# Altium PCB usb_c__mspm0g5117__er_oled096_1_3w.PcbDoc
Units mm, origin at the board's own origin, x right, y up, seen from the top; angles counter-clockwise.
Board outline 64 x 33 mm, 2 copper layers (Top, Bottom), stack 0 mm thick; 30 components, 30 nets, 189 pads, 73 vias.
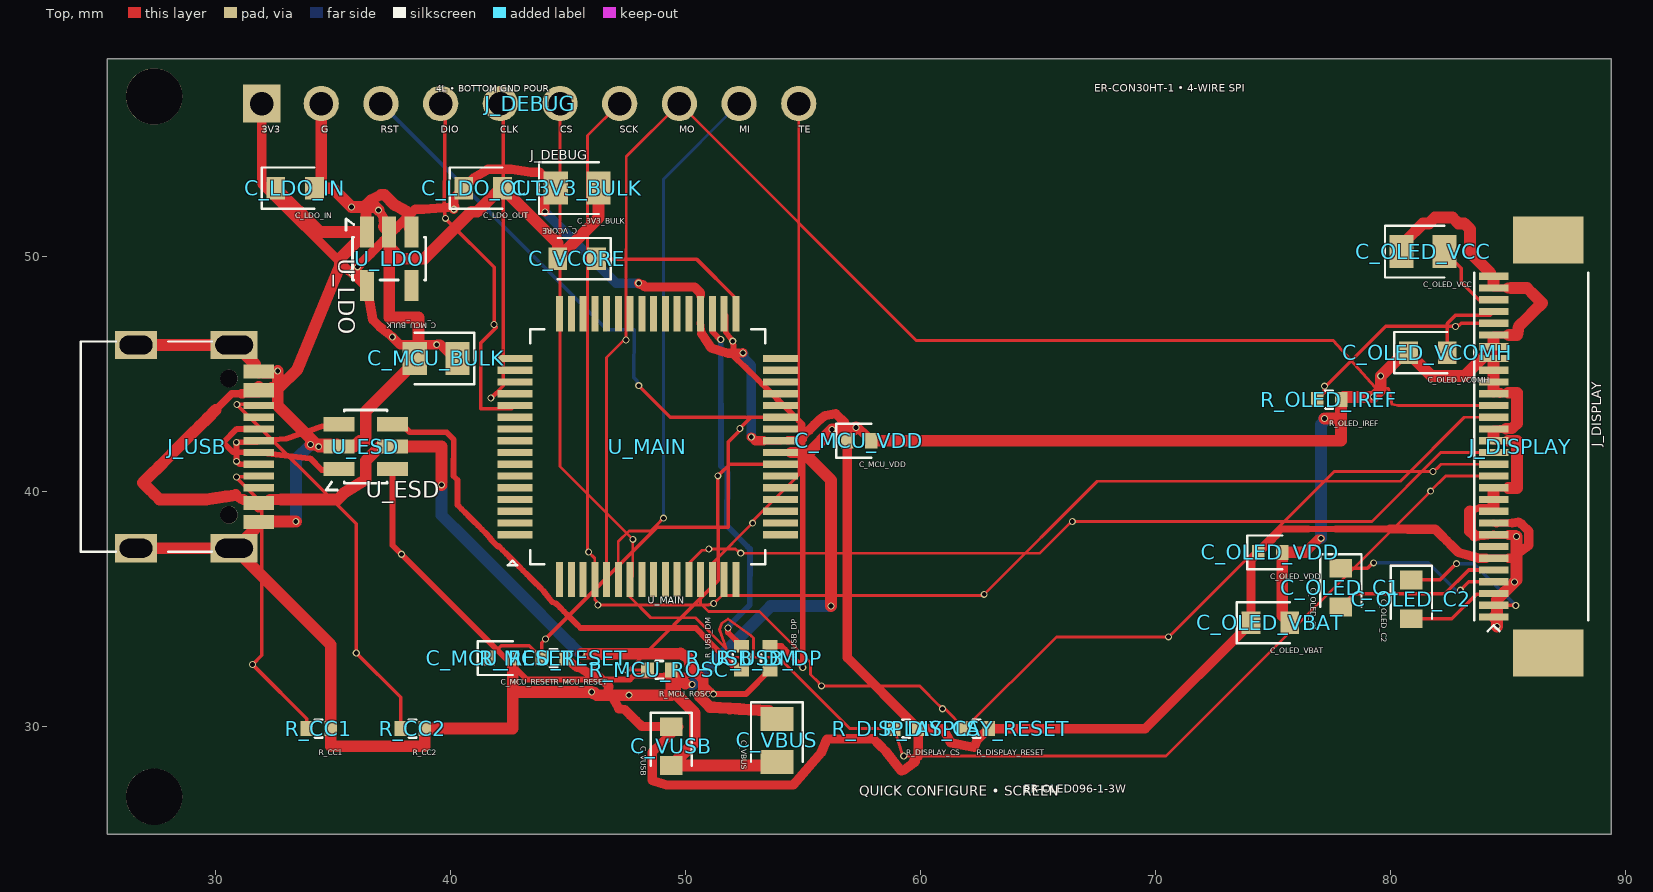
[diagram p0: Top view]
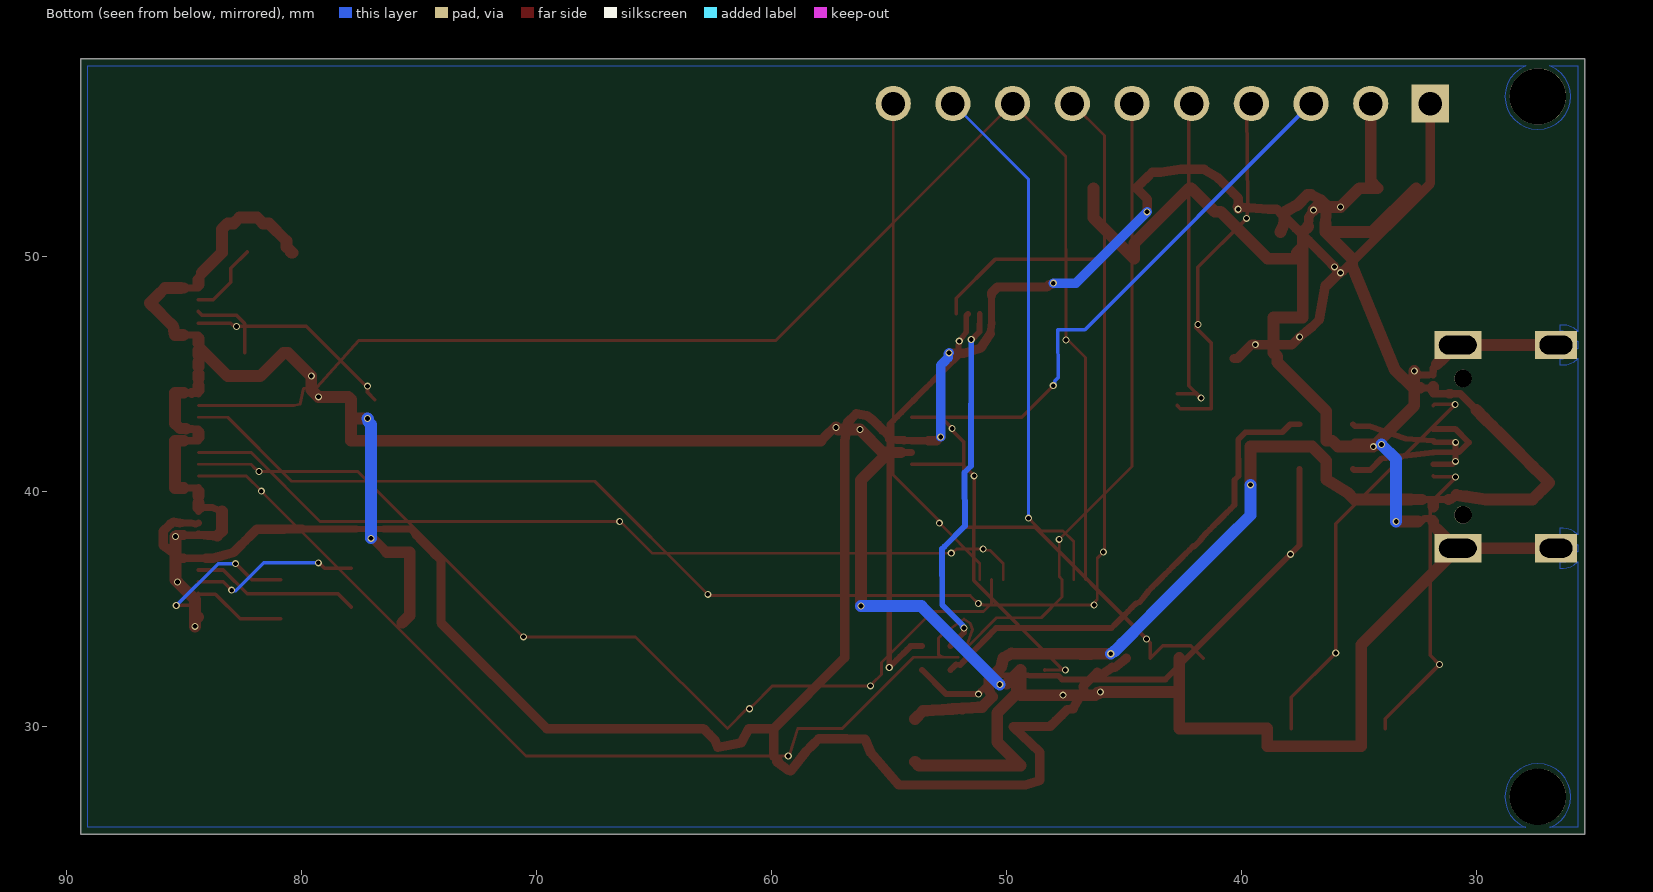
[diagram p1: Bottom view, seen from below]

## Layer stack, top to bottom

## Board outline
25.4,58.4 89.4,58.4 89.4,25.4 25.4,25.4

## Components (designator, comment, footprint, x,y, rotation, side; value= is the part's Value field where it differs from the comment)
C_3V3_BULK "" TSCIRCUIT-2.8500x1.4000mm 45.4,52.9 r0 top
C_LDO_IN "" TSCIRCUIT-2.4500x0.9500mm 33.4,52.9 r0 top
C_LDO_OUT "" TSCIRCUIT-2.4500x0.9500mm 41.4,52.9 r0 top
C_MCU_BULK "" TSCIRCUIT-2.8500x1.4000mm 39.4,45.65 r180 top
C_MCU_RESET "" TSCIRCUIT-1.5600x0.6400mm 42.15,32.9 r0 top
C_MCU_VDD "" TSCIRCUIT-1.5600x0.6400mm 57.4,42.15 r0 top
C_OLED_C1 "" TSCIRCUIT-0.9500x2.4500mm 77.9,35.9 r270 top
C_OLED_C2 "" TSCIRCUIT-0.9500x2.4500mm 80.9,35.4 r270 top
C_OLED_VBAT "" TSCIRCUIT-2.4500x0.9500mm 74.9,34.4 r0 top
C_OLED_VCC "" TSCIRCUIT-2.8500x1.4000mm 81.4,50.2 r0 top
C_OLED_VCOMH "" TSCIRCUIT-2.4500x0.9500mm 81.6,45.9 r0 top
C_OLED_VDD "" TSCIRCUIT-1.5600x0.6400mm 74.9,37.4 r0 top
C_VBUS "" TSCIRCUIT-1.4000x2.8500mm 53.9,29.4 r270 top
C_VCORE "" TSCIRCUIT-2.4500x0.9500mm 45.4,49.9 r180 top
C_VUSB "" TSCIRCUIT-0.9500x2.4500mm 49.4,29.15 r270 top
J_DEBUG "" TSCIRCUIT-24.3600x1.5000mm 43.4,56.5 r0 top
J_DISPLAY "" TSCIRCUIT-4.4500x19.5800mm 86,41.9 r90 top
J_USB "" TSCIRCUIT-6.7732x9.8502mm 29.112,41.9 r90 top
R_CC1 "" TSCIRCUIT-1.5600x0.6400mm 34.4,29.9 r0 top
R_CC2 "" TSCIRCUIT-1.5600x0.6400mm 38.4,29.9 r0 top
R_DISPLAY_CS "" TSCIRCUIT-1.5600x0.6400mm 59.4,29.9 r0 top
R_DISPLAY_RESET "" TSCIRCUIT-1.5600x0.6400mm 62.4,29.9 r0 top
R_MCU_RESET "" TSCIRCUIT-1.5600x0.6400mm 44.4,32.9 r0 top
R_MCU_ROSC "" TSCIRCUIT-1.5600x0.6400mm 48.9,32.4 r0 top
R_OLED_IREF "" TSCIRCUIT-1.5600x0.6400mm 77.4,43.9 r0 top
R_USB_DM "" TSCIRCUIT-0.6400x1.5600mm 52.4,32.9 r90 top
R_USB_DP "" TSCIRCUIT-0.6400x1.5600mm 53.6,32.9 r90 top
U_ESD "" TSCIRCUIT-3.6000x2.5000mm 36.4,41.9 r0 top
U_LDO "" TSCIRCUIT-2.5000x3.6000mm 37.4,49.9 r270 top
U_MAIN "" TSCIRCUIT-12.8000x12.8000mm 48.4,41.9 r0 top

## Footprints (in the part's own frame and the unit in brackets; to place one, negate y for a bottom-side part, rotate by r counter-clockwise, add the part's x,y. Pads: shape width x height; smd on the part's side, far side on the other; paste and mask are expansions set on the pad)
TSCIRCUIT-0.6400x1.5600mm [mm]
  rect 0.54x0.64 smd: 1(-0.51,0) 2(0.51,0)
  silkscreen extent -0.15,-0.38 0.15,0.38
TSCIRCUIT-0.9500x2.4500mm [mm]
  rect 0.8x0.95 smd: 1(-0.825,0) 2(0.825,0)
  silkscreen extent -1.43,-0.87 0.82,0.88
TSCIRCUIT-1.4000x2.8500mm [mm]
  rect 1.025x1.4 smd: 1(-0.913,0) 2(0.913,0)
  silkscreen extent -1.63,-1.1 0.91,1.1
TSCIRCUIT-1.5600x0.6400mm [mm]
  rect 0.54x0.64 smd: 1(-0.51,0) 2(0.51,0)
  silkscreen extent -0.98,-0.72 0.51,0.72
TSCIRCUIT-2.4500x0.9500mm [mm]
  rect 0.8x0.95 smd: 1(-0.825,0) 2(0.825,0)
  silkscreen extent -1.42,-0.88 0.82,0.87
TSCIRCUIT-2.5000x3.6000mm [mm]
  rect 1.325x0.6 smd: 1(-1.138,-0.95) 2(-1.138,0) 3(-1.138,0.95) 4(1.137,0.95) 5(1.137,-0.95)
  silkscreen extent -1.69,-1.84 0.91,1.56
TSCIRCUIT-2.8500x1.4000mm [mm]
  rect 1.025x1.4 smd: 1(-0.913,0) 2(0.913,0)
  silkscreen extent -1.63,-1.1 0.91,1.1
TSCIRCUIT-3.6000x2.5000mm [mm]
  rect 1.325x0.6 smd: 1(-1.138,-0.95) 2(-1.138,0) 3(-1.138,0.95) 4(1.137,0.95) 5(1.137,0) 6(1.137,-0.95)
  silkscreen extent -1.69,-1.84 0.91,1.56
TSCIRCUIT-4.4500x19.5800mm [mm]
  rect 0.3x1.25 smd: 1(-7.25,1.6) 2(-6.75,1.6) 3(-6.25,1.6) 4(-5.75,1.6) 5(-5.25,1.6) 6(-4.75,1.6) 7(-4.25,1.6) 8(-3.75,1.6) 9(-3.25,1.6) 10(-2.75,1.6) 11(-2.25,1.6) 12(-1.75,1.6) 13(-1.25,1.6) 14(-0.75,1.6) 15(-0.25,1.6) 16(0.25,1.6) 17(0.75,1.6) 18(1.25,1.6) 19(1.75,1.6) 20(2.25,1.6) 21(2.75,1.6) 22(3.25,1.6) 23(3.75,1.6) 24(4.25,1.6) 25(4.75,1.6) 26(5.25,1.6) 27(5.75,1.6) 28(6.25,1.6) 29(6.75,1.6) 30(7.25,1.6)
  rect 2x3 smd: 31(8.79,-0.725) 32(-8.79,-0.725)
  silkscreen extent -7.85,-2.42 7.4,2.43
TSCIRCUIT-6.7732x9.8502mm [mm]
  rect 0.3x1.3 smd: 1(-3.35,-2.737) 2(-3.05,-2.737) 3(-2.55,-2.737) 4(-2.25,-2.737) 5(-1.75,-2.737) 6(-1.25,-2.737) 7(-0.75,-2.737) 8(-0.25,-2.737) 9(0.25,-2.737) 10(0.75,-2.737) 11(1.25,-2.737) 12(1.75,-2.737) 13(2.55,-2.737) 14(2.25,-2.737) 15(3.35,-2.737) 16(3.05,-2.737)
  rect 1.2x2 hole 0.8 slot 1.6 at 90 deg: 17(-4.325,-1.693) 18(4.325,-1.693)
  rect 1.2x1.8 hole 0.8 slot 1.4 at 90 deg: 19(4.325,2.487) 20(-4.325,2.487)
  round 0.75 hole 0.75 unplated: NPTH-1(-2.9,-1.468) NPTH-2(2.9,-1.468)
  silkscreen extent -4.47,-0.75 4.47,4.83
TSCIRCUIT-12.8000x12.8000mm [mm]
  rect 1.5x0.3 smd: 1(-5.65,-3.75) 2(-5.65,-3.25) 3(-5.65,-2.75) 4(-5.65,-2.25) 5(-5.65,-1.75) 6(-5.65,-1.25) 7(-5.65,-0.75) 8(-5.65,-0.25) 9(-5.65,0.25) 10(-5.65,0.75) 11(-5.65,1.25) 12(-5.65,1.75) 13(-5.65,2.25) 14(-5.65,2.75) 15(-5.65,3.25) 16(-5.65,3.75) 33(5.65,3.75) 34(5.65,3.25) 35(5.65,2.75) 36(5.65,2.25) 37(5.65,1.75) 38(5.65,1.25) 39(5.65,0.75) 40(5.65,0.25) 41(5.65,-0.25) 42(5.65,-0.75) 43(5.65,-1.25) 44(5.65,-1.75) 45(5.65,-2.25) 46(5.65,-2.75) 47(5.65,-3.25) 48(5.65,-3.75)
  rect 0.3x1.5 smd: 17(-3.75,5.65) 18(-3.25,5.65) 19(-2.75,5.65) 20(-2.25,5.65) 21(-1.75,5.65) 22(-1.25,5.65) 23(-0.75,5.65) 24(-0.25,5.65) 25(0.25,5.65) 26(0.75,5.65) 27(1.25,5.65) 28(1.75,5.65) 29(2.25,5.65) 30(2.75,5.65) 31(3.25,5.65) 32(3.75,5.65) 49(3.75,-5.65) 50(3.25,-5.65) 51(2.75,-5.65) 52(2.25,-5.65) 53(1.75,-5.65) 54(1.25,-5.65) 55(0.75,-5.65) 56(0.25,-5.65) 57(-0.25,-5.65) 58(-0.75,-5.65) 59(-1.25,-5.65) 60(-1.75,-5.65) 61(-2.25,-5.65) 62(-2.75,-5.65) 63(-3.25,-5.65) 64(-3.75,-5.65)
  silkscreen extent -5.95,-5.05 5,5
TSCIRCUIT-24.3600x1.5000mm [mm]
  rect 1.6x1.6 hole 1: 1(-11.43,0)
  round 1.5 hole 1: 2(-8.89,0) 3(-6.35,0) 4(-3.81,0) 5(-1.27,0) 6(1.27,0) 7(3.81,0) 8(6.35,0) 9(8.89,0) 10(11.43,0)

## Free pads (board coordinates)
  round 2.4 hole 2.4 unplated: NPTH-3(27.4,27) NPTH-4(27.4,56.8)

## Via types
v1: diameter 0.3, hole 0.2, Top to Bottom, 73 vias

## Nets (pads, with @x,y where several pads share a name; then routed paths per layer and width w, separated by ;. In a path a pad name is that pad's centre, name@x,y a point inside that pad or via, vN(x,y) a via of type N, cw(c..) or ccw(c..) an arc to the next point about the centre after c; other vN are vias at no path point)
".J_DEBUG > .pin4 to .U_MAIN > .pin12": J_DEBUG.4 U_MAIN.12 | length 15.7
  Top w0.15: J_DEBUG.4 39.795,56.295 39.751,52.199 v1(39.795,51.614) 39.878,51.531 39.878,51.522 41.864,49.535 v1(41.864,47.097) 41.955,47.006 41.955,46.969 41.306,46.32 41.306,43.516 42.616,43.516 U_MAIN.12
".J_DEBUG > .pin5 to .U_MAIN > .pin13": J_DEBUG.5 U_MAIN.13 | length 13.9
  Top w0.15: J_DEBUG.5 42.256,56.374 42.256,56.303 42.256,44.497 v1(41.728,43.969) 41.772,44.013 41.807,44.013 41.943,44.15 U_MAIN.13
".J_DISPLAY > .pin2 to .C_OLED_C2 > .pin1": C_OLED_C2.1 J_DISPLAY.2 | length 6.4
  Top w0.15: C_OLED_C2.1 82.112,36.225 82.669,36.782 82.68,36.782 v1(82.818,36.92) ; J_DISPLAY.2 84.409,35.141 v1(85.341,35.141)
  Bottom w0.15: v1(82.818,36.92) 83.561,36.921 85.333,35.149 v1(85.341,35.141)
".J_DISPLAY > .pin3 to .C_OLED_C2 > .pin2": C_OLED_C2.2 J_DISPLAY.3 | length 3.9
  Top w0.15: C_OLED_C2.2 82.623,34.575 83.672,35.625 84.375,35.625 J_DISPLAY.3
".J_DISPLAY > .pin4 to .C_OLED_C1 > .pin1": C_OLED_C1.1 J_DISPLAY.4 | length 7.3
  Top w0.15: C_OLED_C1.1 79.031,36.725 79.277,36.971 v1(79.293,36.955) ; v1(82.985,35.79) 83.345,36.15 J_DISPLAY.4
  Bottom w0.15: v1(79.293,36.955) 81.626,36.955 82.813,35.768 82.963,35.768 v1(82.985,35.79)
".J_DISPLAY > .pin5 to .C_OLED_C1 > .pin2": C_OLED_C1.2 J_DISPLAY.5 | length 7.2
  Top w0.15: C_OLED_C1.2 78.458,35.633 82.322,35.633 83.339,36.65 J_DISPLAY.5
".J_DISPLAY > .pin26 to .R_OLED_IREF > .pin1": J_DISPLAY.26 R_OLED_IREF.1 | length 9
  Top w0.15: R_OLED_IREF.1 77.203,44.213 v1(77.203,44.474) v1@77.232,44.445 ; v1@77.233,44.445 79.804,47.015 v1(82.781,47.014) 82.834,47.069 82.934,47.069 83.015,47.15 J_DISPLAY.26
".J_DISPLAY > .pin27 to .C_OLED_VCOMH > .pin2": C_OLED_VCOMH.2 J_DISPLAY.27 | length 3.4
  Top w0.15: C_OLED_VCOMH.2 82.424,47.137 82.788,47.5 84.25,47.5 J_DISPLAY.27
".J_DISPLAY > .pin28 to .C_OLED_VCC > .pin2": C_OLED_VCC.2 J_DISPLAY.28 | length 3.3
  Top w0.15: C_OLED_VCC.2 83.017,49.496 83.017,48.899 83.766,48.15 J_DISPLAY.28
".U_MAIN > .pin42 to .R_MCU_ROSC > .pin1": R_MCU_ROSC.1 U_MAIN.42 | length 13.7
  Top w0.15: R_MCU_ROSC.1 48.376,32.386 v1(47.505,32.396) 47.533,32.405 47.61,32.405 51.41,36.205 v1(51.384,40.658) 51.457,40.732 51.473,40.732 51.891,41.15 U_MAIN.42
DISPLAY_CS_N: J_DEBUG.6 J_DISPLAY.13 R_DISPLAY_CS.1 U_MAIN.58 | length 71.1
  Top w0.12: J_DEBUG.6 44.67,41.055 47.714,38.011 v1(47.768,37.957) 47.768,36.368 U_MAIN.58 47.65,35.5 48.534,34.616 50.433,34.616 51.74,33.309 51.46,34.115 51.55,34.385 51.82,34.565 52.81,33.845 52.9,33.755 52.9,33.035 52.72,32.945 52.074,32.939 53.973,32.939 57.003,29.909 58.881,29.909 R_DISPLAY_CS.1 59.244,28.783 v1(59.298,28.731) 70.461,28.73 81.611,39.88 81.611,39.896 v1(81.721,40.006) 82.365,40.65 J_DISPLAY.13
DISPLAY_DC: J_DISPLAY.15 U_MAIN.53 | length 37
  Top w0.12: U_MAIN.53 50.15,36.929 50.709,37.488 50.95,37.488 v1(51.006,37.544) 52.139,37.544 52.221,37.462 52.273,37.462 v1(52.361,37.366) 65.089,37.366 66.346,38.623 66.378,38.623 v1(66.472,38.717) 79.219,38.717 82.152,41.65 J_DISPLAY.15
DISPLAY_MISO: J_DEBUG.9 U_MAIN.59 | length 22.9
  Top w0.12: U_MAIN.59 47.15,37.857 47.604,38.312 48.533,38.312 48.937,38.716 48.937,38.722 v1(49.071,38.856)
  Bottom w0.12: v1(49.071,38.856) 49.071,53.281 J_DEBUG.9
DISPLAY_MOSI: J_DEBUG.8 J_DISPLAY.19 U_MAIN.60 | length 61.9
  Top w0.12: U_MAIN.60 46.65,45.694 47.389,46.432 47.483,46.432 v1(47.48,46.438) 47.489,54.239 J_DEBUG.8 59.832,46.418 77.574,46.418 79.36,44.42 79.453,44.453 79.923,44.375 80.08,43.7 80.342,43.65 J_DISPLAY.19
DISPLAY_RESET_N: J_DISPLAY.14 R_DISPLAY_RESET.1 U_MAIN.52 | length 42
  Top w0.12: U_MAIN.52 50.65,35.224 50.985,34.889 53.162,34.889 55.335,32.716 55.335,32.208 55.682,31.861 55.682,31.83 v1(55.794,31.718) 59.976,31.718 60.805,30.889 ; 60.806,30.889 v1(60.951,30.744) 61.046,30.744 R_DISPLAY_RESET.1 65.795,33.805 v1(70.565,33.805) 70.675,33.915 70.692,33.915 77.617,40.84 v1(81.823,40.84) 81.943,40.96 81.979,40.96 82.169,41.15 J_DISPLAY.14
DISPLAY_SCLK: J_DEBUG.7 J_DISPLAY.18 U_MAIN.61 | length 63.5
  Top w0.12: J_DEBUG.7 45.843,55.133 45.843,37.566 45.843,37.459 v1(45.887,37.415) 46.15,37.152 U_MAIN.61 46.15,35.395 46.225,35.32 46.225,35.215 v1(46.278,35.162) 51.003,35.162 51.02,35.179 51.166,35.179 v1(51.211,35.224) 51.557,35.57 62.674,35.57 v1(62.718,35.614) 67.532,40.428 73.719,40.428 80.43,40.428 83.152,43.15 J_DISPLAY.18
DISPLAY_TE: J_DEBUG.10 U_MAIN.51 | length 21.8
  Top w0.12: U_MAIN.51 51.15,36.925 v1(52.869,38.644) 52.928,38.703 52.928,38.788 54.83,40.691 J_DEBUG.10
GND: C_3V3_BULK.2 C_LDO_IN.2 C_LDO_OUT.2 C_MCU_BULK.2 C_MCU_RESET.2 C_MCU_VDD.2 C_OLED_VBAT.2 C_OLED_VCC.1 C_OLED_VCOMH.1 C_OLED_VDD.2 C_VBUS.2 C_VCORE.2 C_VUSB.2 J_DEBUG.2 J_DISPLAY.1 J_DISPLAY.8 J_DISPLAY.10 J_DISPLAY.11 J_DISPLAY.12 J_DISPLAY.16 J_DISPLAY.17 J_DISPLAY.20 J_DISPLAY.21 J_DISPLAY.22 J_DISPLAY.23 J_DISPLAY.24 J_DISPLAY.25 J_DISPLAY.29 J_DISPLAY.30 J_USB.1 J_USB.2 J_USB.15 J_USB.16 J_USB.17 J_USB.18 J_USB.19 J_USB.20 R_CC1.2 R_CC2.2 R_MCU_ROSC.2 R_OLED_IREF.2 U_ESD.2 U_LDO.2 U_MAIN.41 | length 194.5
  Top w0.275: J_USB.1@31.849,38.7 J_USB.2
  Top w0.288: J_USB.16@31.849,45.1 J_USB.16 J_USB.16@31.945,44.961
  Top w0.3: J_USB.1@31.699,38.4 J_USB.1 J_USB.1@31.849,38.7 ; 31.699,45.4 J_USB.15 J_USB.16@31.849,45.1 ; J_USB.2 31.945,38.839 32.037,38.85 32.13,38.85 32.224,38.85 32.36,38.714 J_USB.2@32.499,38.714 ; J_USB.16@31.945,44.961 32.037,44.95 32.13,44.95 32.224,44.95 32.318,44.95 32.412,44.95 J_USB.16@32.487,44.95 ; 50.002,31.808 v1(50.293,31.776) ; U_MAIN.41@54.496,41.65 U_MAIN.41 54.377,41.65 U_MAIN.41@54.639,41.65 ; 83.4,39.15 83.8,39.3 84.2,39.3 J_DISPLAY.10 J_DISPLAY.10@84.4,39.3 ; J_DISPLAY.24@84.25,46 J_DISPLAY.24 ; 84.25,49.3 J_DISPLAY.30 J_DISPLAY.30@84.4,49 ; J_DISPLAY.8 84.493,38.129 85.025,38.129 ; J_DISPLAY.11@84.4,39.5 J_DISPLAY.11 84.4,39.8 ; J_DISPLAY.12@84.4,40 J_DISPLAY.12 84.408,40.142 84.734,40.142 85.025,40.142 ; 84.4,42.3 J_DISPLAY.16 85.025,42.15 ; J_DISPLAY.17@84.4,42.5 J_DISPLAY.17 J_DISPLAY.17@84.664,42.65 ; J_DISPLAY.20@84.4,44.3 J_DISPLAY.20 J_DISPLAY.20@84.681,44.173 ; J_DISPLAY.21@84.4,44.5 J_DISPLAY.21 84.4,44.8 ; J_DISPLAY.22@84.4,45 J_DISPLAY.22 J_DISPLAY.22@84.4,45.3 ; J_DISPLAY.23@84.4,45.5 J_DISPLAY.23 84.4,45.8 ; J_DISPLAY.24@84.4,46 J_DISPLAY.24 ; J_DISPLAY.24@84.4,46.3 J_DISPLAY.24 ; J_DISPLAY.25@84.4,46.5 J_DISPLAY.25 84.494,46.65 84.587,46.65 84.681,46.65 84.775,46.65 84.869,46.65 84.962,46.65 85.025,46.65 ; 84.4,48.8 J_DISPLAY.29 84.494,48.65 84.587,48.65 84.681,48.65 84.775,48.65 84.869,48.65 84.962,48.65 85.025,48.65 ; J_DISPLAY.20@84.705,44.197 84.962,44.197 85.025,44.197
  Top w0.325: v1(57.268,42.712) v1@57.387,42.673 ; v1@76.932,37.951 76.986,37.951 v1(77.055,37.998)
  Top w0.338: J_DISPLAY.17@84.664,42.65 J_DISPLAY.17@84.923,42.658
  Top w0.375: J_USB.16@32.487,44.95 32.496,44.959 32.5,44.963 32.563,45.026 32.566,45.029 v1(32.655,45.118)
  Top w0.377: J_DISPLAY.8@83.775,38.111 84,38.125 J_DISPLAY.8
  Top w0.4: v1(36.949,51.965) 37.15,51.65 U_LDO.2@37.175,51.263 ; v1@57.387,42.673 57.649,42.412 C_MCU_VDD.2 ; 83.6,38.1 J_DISPLAY.8@83.775,38.111
  Top w0.403: J_DISPLAY.20@84.681,44.173 J_DISPLAY.20@84.705,44.197
  Top w0.425: 76.38,37.4 76.656,37.676 v1@76.932,37.951 ; 85.025,38.129 85.322,38.129 v1(85.375,38.075)
  Top w0.475: U_MAIN.41@54.496,41.65 54.941,41.65 ; U_MAIN.41@54.639,41.65 54.9,41.65 ; 83.4,38.3 83.6,38.1 ; J_DISPLAY.1 84.541,34.509 v1(84.541,34.25) ; J_DISPLAY.17@84.923,42.658 85.181,42.666 85.4,42.884 ; 85.025,46.65 85.056,46.65 ; 85.025,48.65 85.056,48.65 85.15,48.65
  Top w0.5: J_USB.20 J_USB.17 ; J_USB.19 J_USB.18 ; J_USB.18 30.874,46.225 31.474,45.625 31.699,45.4 ; J_USB.1@31.699,38.4 31.474,38.175 30.874,37.575 J_USB.17 34.91,33.471 R_CC1.2 34.91,29.15 38.91,29.15 R_CC2.2 42.66,29.9 C_MCU_RESET.2 42.66,31.461 v1(46.015,31.461) 46.062,31.414 46.148,31.414 46.239,31.323 46.695,31.323 47.152,31.323 v1(47.609,31.323) 49.41,31.323 R_MCU_ROSC.2 ; 32.499,38.714 v1(33.43,38.714) ; v1(32.655,45.118) 32.655,43.645 v1(34.4,41.9) U_ESD.2 ; v1(34.055,41.989) 35.173,41.989 U_ESD.2 ; J_DEBUG.2 34.51,53.185 C_LDO_IN.2 34.608,52.9 34.991,52.9 35.343,52.548 35.694,52.197 35.703,52.197 v1(35.8,52.1) 36.814,52.1 v1(36.949,51.965) ; U_LDO.2@37.175,51.263 U_LDO.2 ; C_3V3_BULK.2 46.313,51.637 C_VCORE.2 44.575,50.55 C_LDO_OUT.2 42.15,52.9 41.15,51.9 40.9,51.9 38.9,49.9 37.65,49.9 37.65,50.15 37.4,50.4 U_LDO.2 ; 50.002,31.808 49.706,32.104 R_MCU_ROSC.2 ; C_VBUS.2 53.737,28.325 C_VUSB.2 50.4,29.325 50.4,30.567 49.567,31.4 49.567,32.233 49.41,32.39 R_MCU_ROSC.2 ; 54.9,41.65 55.213,41.463 56.205,40.47 v1(56.205,35.114) ; 54.941,41.65 55.268,41.65 v1(56.243,42.625) 57.181,42.625 v1(57.268,42.712) ; C_MCU_VDD.2 58.403,42.15 58.896,42.15 59.39,42.15 59.883,42.15 60.376,42.15 60.869,42.15 61.363,42.15 61.856,42.15 62.349,42.15 62.842,42.15 63.336,42.15 63.829,42.15 64.322,42.15 64.815,42.15 65.309,42.15 65.802,42.15 66.295,42.15 66.788,42.15 67.282,42.15 67.775,42.15 68.268,42.15 68.761,42.15 69.255,42.15 69.748,42.15 70.241,42.15 70.734,42.15 71.228,42.15 71.721,42.15 72.214,42.15 77.91,42.15 R_OLED_IREF.2 ; C_OLED_VBAT.2 75.41,34.715 C_OLED_VDD.2 75.895,37.4 76.38,37.4 ; v1(77.2,43.1) 77.91,43.1 R_OLED_IREF.2 ; C_OLED_VCC.1 80.437,50.15 80.4,50.15 80.65,50.4 80.65,50.65 81.4,51.4 81.65,51.4 81.9,51.65 82.65,51.65 82.9,51.4 83.15,51.4 83.4,51.15 83.4,50.15 84.25,49.3 ; 83.4,38.3 83.4,38.6 83.4,38.9 83.4,39.15 ; J_DISPLAY.24@84.25,46 83.15,44.9 81.775,44.9 C_OLED_VCOMH.1 80.591,45.9 v1(79.593,44.902) 79.593,44.612 79.593,44.322 79.298,44.027 v1(79.287,44.016) 78.867,44.016 78.446,44.016 78.026,44.016 R_OLED_IREF.2 ; J_DISPLAY.10@84.4,39.3 J_DISPLAY.11@84.4,39.5 ; 84.4,39.8 84.4,40 ; 84.4,42.3 84.4,42.5 ; J_DISPLAY.20@84.4,44.3 J_DISPLAY.21@84.4,44.5 ; 84.4,44.8 84.4,45 ; 84.4,45.3 84.4,45.5 ; 84.4,45.8 J_DISPLAY.24@84.4,46 ; 84.4,46.3 84.4,46.5 ; 84.4,48.8 84.4,49 ; v1(84.541,34.25) 84.541,35.389 v1(85.29,36.138) 85.375,36.223 v1(85.375,38.075) ; 85.025,40.142 85.392,40.142 85.4,40.15 85.4,42.15 85.025,42.15 ; 85.025,44.197 85.4,44.197 85.4,43.249 85.4,42.884 ; 85.056,46.65 85.106,46.65 85.4,46.65 85.469,47.013 85.8,47.344 86.132,47.676 86.464,48.008 86.142,48.329 85.821,48.65 85.486,48.65 85.15,48.65 ; U_ESD.2 35.9,41.9 36.15,42.15 36.4,42.15 36.4,43.4 38.487,45.488 C_MCU_BULK.2 38.487,45.738 38.65,45.9 38.65,47.4 37.4,47.4 U_LDO.2
  Bottom w0.5: v1(33.43,38.714) 33.43,41.364 v1(34.055,41.989) ; v1(50.293,31.776) 53.632,35.114 v1(56.205,35.114) ; v1(77.055,37.998) 77.055,38.482 77.055,38.966 77.055,39.45 77.055,39.934 77.055,40.418 77.055,40.902 77.055,41.386 77.055,41.87 77.055,42.354 77.055,42.838 77.176,42.959 77.176,43.076 v1(77.2,43.1)
MAIN_RESET: C_MCU_RESET.1 J_DEBUG.3 R_MCU_RESET.1 U_MAIN.38 | length 43.5
  Top w0.15: C_MCU_RESET.1 42.17,33.43 43.36,33.43 R_MCU_RESET.1 43.89,33.555 43.957,33.622 v1(44.05,33.715) 48.812,38.477 51.826,38.477 51.826,42.099 52.27,42.542 52.27,42.623 v1(52.321,42.674) 52.797,43.15 U_MAIN.38 49.366,43.15 v1(48.021,44.495)
  Bottom w0.15: J_DEBUG.3 46.671,46.879 47.821,46.879 47.817,44.839 47.963,44.691 47.963,44.553 v1(48.021,44.495)
MSP_VCORE: C_VCORE.1 U_MAIN.32 | length 7.3
  Top w0.15: C_VCORE.1 46.26,49.865 50.497,49.865 52.15,48.212 U_MAIN.32
usb-dm-mcu: R_USB_DM.2 U_MAIN.30 | length 15.5
  Top w0.25: U_MAIN.30 51.156,46.787 51.494,46.445 v1(51.511,46.456) ; v1(51.817,34.18) 51.817,33.993 R_USB_DM.2
  Bottom w0.25: v1(51.511,46.456) 51.522,41.072 51.794,40.799 51.781,38.519 52.652,37.648 52.752,37.555 52.745,35.187 52.744,35.162 51.879,34.297 51.879,34.242 v1(51.817,34.18)
usb-dm-phy: R_USB_DM.1 U_ESD.4 | length 20.8
  Top w0.25: U_ESD.4 37.736,42.85 37.935,42.85 38.104,42.681 38.273,42.511 39.85,42.5 40.15,42.2 40.136,40.649 40.305,40.479 40.305,40.268 40.305,40.056 40.305,39.845 40.305,39.633 40.305,39.422 40.48,39.247 40.655,39.073 40.829,38.898 41.004,38.724 41.178,38.549 41.353,38.374 41.527,38.2 41.775,37.9 42.025,37.65 42.051,37.676 42.225,37.502 42.4,37.327 42.575,37.153 42.749,36.978 42.924,36.804 43.098,36.629 43.273,36.454 43.447,36.28 43.622,36.105 43.796,35.931 43.971,35.756 44.338,35.275 44.495,35.233 44.669,35.058 44.844,34.884 45.018,34.709 45.193,34.534 45.367,34.36 45.542,34.185 45.787,34.185 46.033,34.185 46.278,34.185 46.524,34.184 46.769,34.184 47.014,34.184 47.26,34.184 47.505,34.183 47.751,34.183 47.996,34.183 48.242,34.183 48.487,34.182 48.732,34.182 48.978,34.182 49.223,34.182 49.469,34.181 49.714,34.181 49.959,34.181 50.205,34.181 50.45,34.18 50.62,34.006 50.79,33.832 50.96,33.657 51.129,33.483 51.299,33.309 51.469,33.134 51.638,32.96 51.808,32.786 51.978,32.611 52.153,32.637 52.277,32.513 R_USB_DM.1
usb-dm-port: J_USB.7 J_USB.9 U_ESD.3 | length 6.4
  Top w0.25: J_USB.7 31.042,41.15 30.906,41.286 v1(30.904,41.272) 30.904,42.001 30.879,42.026 30.879,42.084 v1(30.896,42.081) 31.79,42.091 J_USB.9 33.017,42.235 34.547,42.768 35.18,42.767 U_ESD.3
usb-dp-mcu: R_USB_DP.2 U_MAIN.31 | length 18.2
  Top w0.225: 51.722,46.778 51.872,46.584 v1(52.021,46.389)
  Top w0.25: U_MAIN.31 51.722,47.478 51.722,47.245 51.722,47.011 51.722,46.778 ; v1(52.021,46.389) 52.022,46.362 52.022,46.264 52.059,46.227 52.058,46.003 52.058,45.78 52.025,45.775 52.577,45.261 52.75,45.088 52.923,44.915 53.096,44.742 53.269,44.569 53.442,44.396 53.615,44.223 53.788,44.05 53.962,43.877 54.135,43.704 54.308,43.531 54.481,43.358 54.654,43.185 54.827,43.012 55,42.839 55,42.593 55,42.347 55,42.101 55,41.855 55,41.608 55,41.362 55,41.116 55,40.87 55,40.624 55,40.378 55,40.131 55,39.885 55,39.639 55,39.393 55,39.147 55,38.901 55,38.654 55,38.408 55,38.162 55,37.916 55,37.67 55,37.424 55,37.177 55,36.931 55,36.685 55,36.439 55,36.193 55,35.946 55,35.7 55,35.454 55,35.208 55,34.962 55,34.716 55,34.469 55,34.223 55,33.977 55,33.731 55,33.485 55,33.239 55,32.992 55,32.746 v1(55,32.5) 54.981,32.519 54.832,32.668 54.684,32.816 54.535,32.965 54.387,33.113 54.238,33.262 54.09,33.41 53.845,33.41 R_USB_DP.2
usb-dp-phy: R_USB_DP.1 U_ESD.6 | length 22.5
  Top w0.25: U_ESD.6 37.537,37.704 37.893,37.348 v1(37.921,37.32) 43.244,31.997 47.645,31.995 47.804,32.141 50.329,32.174 50.467,32.155 51.111,31.501 51.11,31.461 v1(51.206,31.365) 52.575,31.365 R_USB_DP.1
usb-dp-port: J_USB.8 J_USB.10 U_ESD.1 | length 7.1
  Top w0.25: J_USB.10 30.918,42.655 30.335,42.073 30.758,41.664 J_USB.8 34.035,41.401 34.533,40.904 35.217,40.904 U_ESD.1
USB_CC1: J_USB.6 R_CC1.1 | length 13.2
  Top w0.15: J_USB.6 31.807,40.608 v1(30.906,40.608) 30.966,40.548 30.966,40.514 31.982,39.499 31.982,39.436 31.982,33.021 v1(31.585,32.624) 31.71,32.499 31.714,32.499 33.89,30.323 R_CC1.1
USB_CC2: J_USB.12 R_CC2.1 | length 17.6
  Top w0.15: J_USB.12 31.803,43.696 v1(30.916,43.696) 30.946,43.666 30.947,43.666 35.998,38.615 v1(35.998,33.119) 36.001,33.116 37.89,31.227 R_CC2.1
VBUS5: C_LDO_IN.1 C_VBUS.1 J_USB.3 J_USB.4 J_USB.13 J_USB.14 U_ESD.5 U_LDO.1 U_LDO.3 | length 60.4
  Top w0.3: 31.193,44.15 31.199,44.15 31.287,44.15 31.38,44.15 31.474,44.15 31.568,44.15 31.662,44.15 31.755,44.15 J_USB.14 J_USB.14@31.849,44.3 ; J_USB.4@31.199,39.65 31.287,39.65 31.38,39.65 31.474,39.65 31.568,39.65 31.661,39.65 31.755,39.65 J_USB.4 ; J_USB.3@31.849,39.5 J_USB.4 ; J_USB.13 32.1,44.4 J_USB.13@32.4,44.4 ; J_USB.4@32.328,39.65 J_USB.4
  Top w0.325: 30.018,43.461 30.362,43.806 30.706,44.15 31.099,44.15
  Top w0.4: 30.869,39.837 31.099,39.65 31.193,39.65 31.199,39.65 ; 31.099,44.15 31.193,44.15
  Top w0.437: 50.535,32.221 50.765,31.983 50.765,31.546
  Top w0.45: 36.4,52.181 36.619,52.4 37.056,52.619 ; 50.234,32.523 50.535,32.221 ; 50.619,31.254 50.765,31.546
  Top w0.475: J_USB.4@32.328,39.65 32.807,39.65 ; 36.4,52.181 36.417,51.8 U_LDO.1@36.433,51.419 ; 50.619,31.254 50.838,31.035 51.056,30.817
  Top w0.5: 30.018,43.461 29.673,43.117 29.329,42.772 28.985,42.428 28.64,42.084 28.296,41.739 27.951,41.395 27.607,41.051 27.263,40.706 26.918,40.362 27.156,40.125 27.393,39.887 27.63,39.65 28.126,39.65 28.621,39.65 29.117,39.65 29.612,39.65 30.031,39.713 30.45,39.775 30.869,39.837 ; J_USB.3 J_USB.3@31.849,39.5 ; J_USB.13@31.849,44.3 J_USB.13 ; J_USB.13@32.4,44.4 32.7,44.4 33.5,45.2 35.3,49.6 35.3,49.887 U_LDO.1 ; C_LDO_IN.1 34.438,51.038 U_LDO.1 ; 32.807,39.65 33.287,39.65 33.766,39.65 34.245,39.65 34.724,39.65 35.203,39.65 35.507,39.954 36.4,40.5 36.4,41.3 37,41.9 U_ESD.5 39.626,41.9 v1(39.626,40.271) ; U_LDO.1@36.433,51.419 U_LDO.1 ; 37.056,52.619 37.202,52.619 37.64,52.181 38.15,51.9 38.21,51.346 U_LDO.3 ; v1(45.575,33.085) 46.001,33.082 46.427,33.078 46.853,33.075 49.8,33.1 50.15,32.9 50.234,32.523 ; 51.056,30.817 51.474,30.789 51.892,30.761 52.31,30.733 52.728,30.705 53.146,30.677 53.563,30.649 C_VBUS.1
  Bottom w0.5: v1(39.626,40.271) 39.626,39.842 39.626,39.413 39.626,38.983 39.968,38.642 40.309,38.3 40.651,37.959 40.992,37.617 41.334,37.276 41.675,36.934 42.017,36.593 42.358,36.251 42.7,35.909 43.041,35.568 43.383,35.226 43.725,34.885 44.066,34.543 44.408,34.202 44.749,33.86 45.091,33.519 45.432,33.177 45.439,33.177 v1(45.575,33.085)
VCC_3V3: C_3V3_BULK.1 C_LDO_OUT.1 C_MCU_BULK.1 C_MCU_VDD.1 C_OLED_VBAT.1 C_OLED_VDD.1 C_VUSB.1 J_DEBUG.1 J_DISPLAY.6 J_DISPLAY.9 R_DISPLAY_CS.2 R_DISPLAY_RESET.2 R_MCU_RESET.2 U_LDO.5 U_MAIN.29 U_MAIN.40 | length 121.8
  Top w0.262: 76.528,38.399 76.913,38.398 77.297,38.398 77.682,38.397
  Top w0.288: J_DISPLAY.9 84.521,38.601 J_DISPLAY.9@84.61,38.625
  Top w0.3: U_MAIN.29@50.642,47.168 U_MAIN.29 50.65,47.65 50.65,47.75 50.65,47.85 50.65,47.95 50.65,48.05 50.65,48.15 50.65,48.25 50.65,48.3 50.65,48.35 ; U_MAIN.40@53.339,42.15 53.694,42.15 U_MAIN.40 ; 75.128,38.151 75.375,38.401 75.759,38.4 76.144,38.4 76.528,38.399 ; J_DISPLAY.6 84.5,37.15 84.6,37.15 84.7,37.15 84.8,37.15 84.9,37.15 85,37.15 85.025,37.15 ; J_DISPLAY.9@84.61,38.625 84.7,38.65 84.8,38.65 84.9,38.65 85,38.65 85.025,38.65 85.1,38.65
  Top w0.301: J_DISPLAY.6@84.087,37.15 J_DISPLAY.6
  Top w0.312: U_MAIN.40 U_MAIN.40@54.367,42.167 ; 77.682,38.397 78.066,38.397 78.451,38.396 78.835,38.395 79.22,38.395 79.605,38.394 79.989,38.393
  Top w0.331: U_MAIN.29@50.642,47.168 50.7,46.7
  Top w0.343: 85.1,38.65 85.2,38.65
  Top w0.35: U_MAIN.40@54.367,42.167 54.683,42.183 55,42.2 55.045,42.374 55.269,42.598
  Top w0.4: J_DEBUG.1 31.97,53.103 35.705,49.367 35.733,49.367 v1(35.8,49.3) 35.912,49.3 U_LDO.5 ; C_MCU_BULK.1 40.177,45.65 39.566,46.261 39.448,46.261 v1(39.423,46.237) 37.864,46.237 37.554,46.547 v1(37.537,46.564) 37,47 36.7,47.3 U_LDO.5 ; v1(44.029,51.892) 44.023,52.435 C_3V3_BULK.1 44.261,53.126 44.035,53.352 43.809,53.578 43.446,53.578 42.6,53.7 41.6,53.7 41.027,53.352 40.801,53.126 C_LDO_OUT.1 40.363,52.688 40.151,52.476 40.151,52.239 v1(40.151,52.001) 40.2,52.1 38.878,52.009 38.509,52.009 38.238,51.738 37.967,51.467 37.696,51.196 37.425,50.925 37.155,50.655 36.884,50.384 36.613,50.113 36.342,49.842 36.071,49.571 v1(36.05,49.55) 35.873,49.227 35.893,49.227 36.125,48.995 36.357,48.763 U_LDO.5 ; R_MCU_RESET.2 45.4,32.5 45.502,32.506 45.798,32.308 46.094,32.111 46.15,32.3 46.75,31.7 46.686,31.435 46.931,31.194 47.176,30.749 47.421,30.712 47.666,30.47 47.911,30.229 48.156,29.988 48.463,29.988 48.771,29.988 49.079,29.988 49.387,29.988 C_VUSB.1 49.73,29.971 48.6,28.9 48.6,27.7 49.2,27.5 54.6,27.5 55.8,28.9 56.031,29.457 56.425,29.459 56.82,29.461 57.214,29.463 57.609,29.465 58.004,29.467 58.269,29.201 58.534,28.936 59.2,28.1 59.329,28.141 59.8,28.5 59.716,28.528 59.91,28.722 59.91,29.115 59.91,29.507 R_DISPLAY_CS.2 ; v1(48.018,48.857) 48.078,48.797 48.186,48.797 48.29,48.693 50.392,48.693 50.65,48.435 50.65,48.35 ; 50.7,46.7 51.1,46.1 51.843,45.873 52.148,45.881 v1(52.453,45.89) ; v1(52.813,42.311) 52.845,42.279 52.854,42.279 52.983,42.15 U_MAIN.40@53.339,42.15 ; 55.269,42.598 55.493,42.822 55.717,43.046 55.959,43.223 56.4,43.3 56.8,42.9 56.8,42.7 C_MCU_VDD.1 56.89,32.92 R_DISPLAY_CS.2 ; 75.128,38.151 74.882,37.9 74.636,37.65 C_OLED_VDD.1 74.075,37.085 C_OLED_VBAT.1 69.575,29.9 R_DISPLAY_RESET.2 62.662,29.652 62.414,29.404 62.3,29.1 61.3,29.3 60.985,29.9 60.627,29.9 60.268,29.9 R_DISPLAY_CS.2 ; 79.989,38.393 80.374,38.393 80.758,38.392 81.143,38.392 81.527,38.391 81.912,38.39 82.159,38.142 82.406,37.894 82.653,37.646 82.9,37.398 83.773,37.15 J_DISPLAY.6@84.087,37.15 ; 85.025,37.15 85.1,37.15 85.173,37.15 85.192,37.169 85.9,37.7 85.9,38.3 85.6,38.6 85.45,38.693 85.2,38.65
  Bottom w0.4: v1(44.029,51.892) 44.051,51.858 47.052,48.857 v1(48.018,48.857) ; v1(52.453,45.89) 52.496,45.845 52.496,45.679 52.654,45.52 52.813,45.361 52.813,44.98 52.813,44.599 52.813,44.217 52.813,43.836 52.813,43.455 52.813,43.074 52.813,42.692 v1(52.813,42.311)
pads on no net: J_DISPLAY.7 J_DISPLAY.31 J_DISPLAY.32 J_USB.5 J_USB.11 J_USB.NPTH-1 J_USB.NPTH-2 U_LDO.4 U_MAIN.1 U_MAIN.2 U_MAIN.3 U_MAIN.4 U_MAIN.5 U_MAIN.6 U_MAIN.7 U_MAIN.8 U_MAIN.9 U_MAIN.10 U_MAIN.11 U_MAIN.14 U_MAIN.15 U_MAIN.16 U_MAIN.17 U_MAIN.18 U_MAIN.19 U_MAIN.20 U_MAIN.21 U_MAIN.22 U_MAIN.23 U_MAIN.24 U_MAIN.25 U_MAIN.26 U_MAIN.27 U_MAIN.28 U_MAIN.33 U_MAIN.34 U_MAIN.35 U_MAIN.36 U_MAIN.37 U_MAIN.39 U_MAIN.43 U_MAIN.44 U_MAIN.45 U_MAIN.46 U_MAIN.47 U_MAIN.48 U_MAIN.49 U_MAIN.50 U_MAIN.54 U_MAIN.55 U_MAIN.56 U_MAIN.57 U_MAIN.62 U_MAIN.63 U_MAIN.64

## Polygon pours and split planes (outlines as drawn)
GND on Bottom (solid): 26.886,58.1 25.7,58.1 25.7,46.796 25.725,46.826 25.854,46.932 26.001,47.01 26.16,47.059 26.326,47.075 26.476,47.075 26.476,46.825 26.326,46.825 26.209,46.814 26.096,46.779 25.993,46.724 25.902,46.649 25.827,46.558 25.772,46.455 25.747,46.375 25.7,46.375 25.7,46.075 25.747,46.075 25.772,45.996 25.827,45.892 25.902,45.801 25.993,45.726 26.096,45.671 26.209,45.637 26.326,45.625 26.476,45.625 26.476,45.375 26.326,45.375 26.16,45.391 26.001,45.44 25.854,45.518 25.725,45.624 25.7,45.654 25.7,38.146 25.725,38.176 25.854,38.282 26.001,38.36 26.16,38.409 26.326,38.425 26.476,38.425 26.476,38.175 26.326,38.175 26.209,38.163 26.096,38.129 25.993,38.074 25.902,37.999 25.827,37.908 25.772,37.804 25.747,37.725 25.7,37.725 25.7,37.425 25.747,37.425 25.772,37.345 25.827,37.242 25.902,37.151 25.993,37.076 26.096,37.021 26.209,36.986 26.326,36.975 26.476,36.975 26.476,36.725 26.326,36.725 26.16,36.741 26.001,36.79 25.854,36.868 25.725,36.974 25.7,37.004 25.7,25.7 26.886,25.7 26.864,25.707 26.622,25.836 26.41,26.01 26.236,26.222 26.107,26.464 26.027,26.727 26,27 26.027,27.273 26.107,27.536 26.236,27.778 26.41,27.99 26.622,28.164 26.864,28.293 27.127,28.373 27.4,28.4 27.673,28.373 27.936,28.293 28.178,28.164 28.39,27.99 28.564,27.778 28.693,27.536 28.773,27.273 28.8,27 28.773,26.727 28.693,26.464 28.564,26.222 28.39,26.01 28.178,25.836 27.936,25.707 27.914,25.7 89.1,25.7 89.1,58.1 27.914,58.1 27.936,58.093 28.178,57.964 28.39,57.79 28.564,57.578 28.693,57.336 28.773,57.073 28.8,56.8 28.773,56.527 28.693,56.264 28.564,56.022 28.39,55.81 28.178,55.636 27.936,55.507 27.673,55.427 27.4,55.4 27.127,55.427 26.864,55.507 26.622,55.636 26.41,55.81 26.236,56.022 26.107,56.264 26.027,56.527 26,56.8 26.027,57.073 26.107,57.336 26.236,57.578 26.41,57.79 26.622,57.964 26.864,58.093

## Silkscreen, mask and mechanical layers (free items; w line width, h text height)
Top Overlay:
  text "4L • BOTTOM GND POUR" at 39.4,56.9 h0.48
  text "ER-CON30HT-1 • 4-WIRE SPI" at 67.4,56.9 h0.55
  text "ER-OLED096-1-3W" at 64.4,27.05 h0.58
  text "QUICK CONFIGURE • SCREEN" at 57.4,26.9 h0.72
